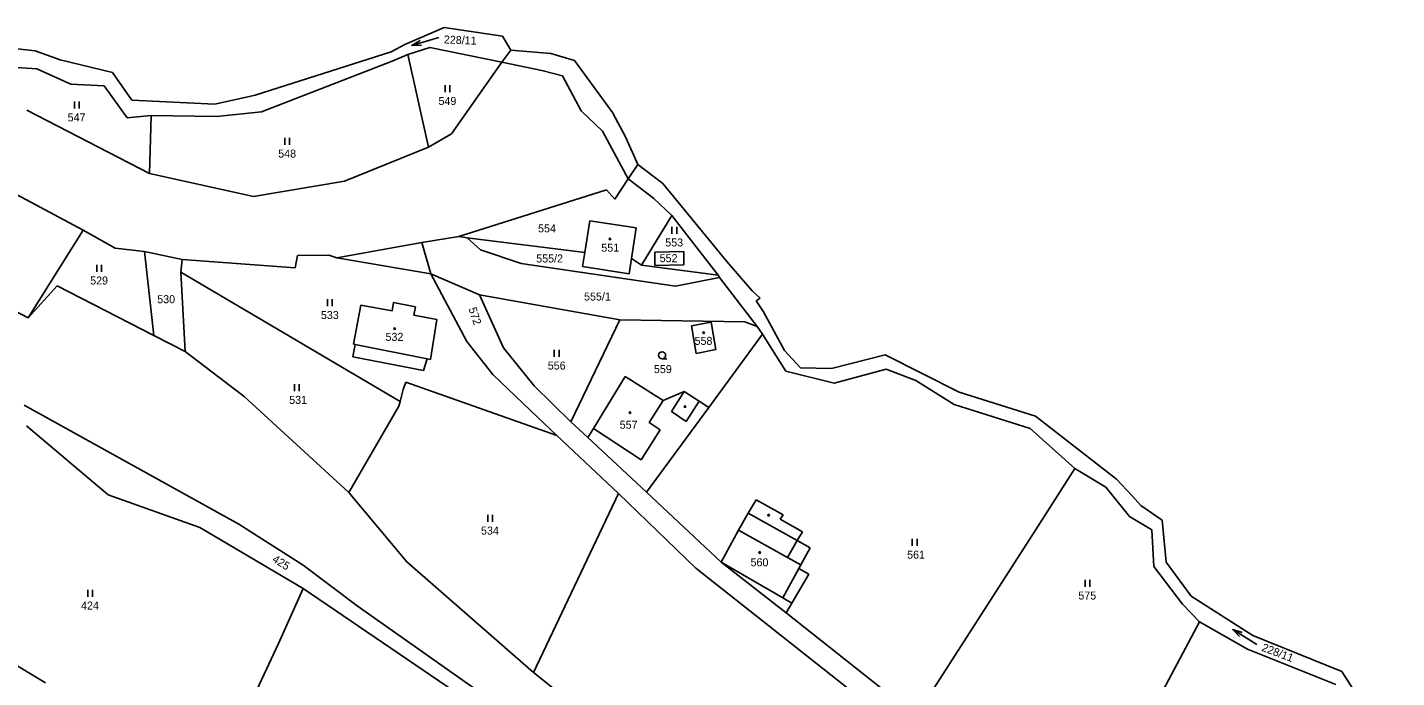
# Model space of a CAD drawing. Extents: x -670359 to -668019, y -978807 to -976674.
# Drawn here: x -668397.5 to -668106.7, y -976872.6 to -976734.6 of the extents above; entities that cross this region are included whole.
import ezdxf

# ---------------------------------------------------------------- set-up
doc = ezdxf.new("R2010")
doc.units = 0
for name, color, linetype in [('Hranice kat_území', 7, 'Continuous'), ('Hranice parcel', 7, 'Continuous'), ('Parcelní čísla', 7, 'Continuous'), ('Vnitřní kresba', 7, 'Continuous'), ('Značky budov', 7, 'Continuous'), ('Značky kultur', 7, 'Continuous')]:
    doc.layers.add(name, color=color, linetype=linetype)

msp = doc.modelspace()

# ---------------------------------------------------------------- linework, layer by layer
at = {"layer": 'Hranice kat_území'}
for points in [[(-668317.37, -976738.24), (-668309.02, -976734.61)], [(-668309.02, -976734.61), (-668296.58, -976736.5)], [(-668296.58, -976736.5), (-668294.82, -976739.45)], [(-668401.56, -976738.95), (-668395.86, -976739.55)], [(-668395.86, -976739.55), (-668390.58, -976741.48)], [(-668349.12, -976748.96), (-668320.23, -976739.79)], [(-668320.23, -976739.79), (-668317.37, -976738.24)], [(-668294.82, -976739.45), (-668286.37, -976740.15)], [(-668390.58, -976741.48), (-668379.43, -976744.15)], [(-668286.37, -976740.15), (-668281.3, -976741.62)], [(-668281.3, -976741.62), (-668273.27, -976752.67)], [(-668379.43, -976744.15), (-668375.33, -976750.07)], [(-668375.33, -976750.07), (-668357.69, -976750.92)], [(-668357.69, -976750.92), (-668349.12, -976748.96)], [(-668273.27, -976752.67), (-668270.5, -976757.82)], [(-668270.5, -976757.82), (-668267.83, -976763.68)], [(-668267.83, -976763.68), (-668262.57, -976767.7)], [(-668262.57, -976767.7), (-668248.96, -976784.27)], [(-668248.96, -976784.27), (-668243.58, -976790.53)], [(-668243.58, -976790.53), (-668241.91, -976792.09)], [(-668241.91, -976792.09), (-668242.75, -976792.62)], [(-668242.75, -976792.62), (-668241.2, -976794.95)], [(-668241.2, -976794.95), (-668236.71, -976803.16)], [(-668236.71, -976803.16), (-668233.34, -976806.82)], [(-668233.34, -976806.82), (-668226.72, -976807)], [(-668226.72, -976807), (-668215.36, -976804.09)], [(-668215.36, -976804.09), (-668199.61, -976811.98)], [(-668199.61, -976811.98), (-668183.37, -976817.09)], [(-668183.37, -976817.09), (-668166.16, -976830.45)], [(-668166.16, -976830.45), (-668162.87, -976834.03)], [(-668161.05, -976836.02), (-668162.87, -976834.03)], [(-668161.05, -976836.02), (-668156.53, -976839.16)], [(-668156.53, -976839.16), (-668155.66, -976848.08)], [(-668155.66, -976848.08), (-668150.37, -976855.32)], [(-668150.37, -976855.32), (-668137.24, -976863.65)], [(-668137.24, -976863.65), (-668118.31, -976871.28)], [(-668118.31, -976871.28), (-668106.7, -976889.43)]]:
    msp.add_lwpolyline(points, dxfattribs=at)
at = {"layer": 'Hranice parcel'}
for points in [[(-668316.7, -976740.34), (-668312.03, -976738.87)], [(-668312.03, -976738.87), (-668296.72, -976741.98)], [(-668347.77, -976752.51), (-668320.02, -976741.74)], [(-668320.02, -976741.74), (-668316.7, -976740.34)], [(-668316.7, -976740.34), (-668312.35, -976759.99)], [(-668307.41, -976757.21), (-668296.72, -976741.98)], [(-668296.72, -976741.98), (-668288.24, -976743.73)], [(-668402.02, -976742.95), (-668395.53, -976743.38)], [(-668395.53, -976743.38), (-668388.26, -976746.62)], [(-668288.24, -976743.73), (-668283.85, -976744.87)], [(-668283.85, -976744.87), (-668279.91, -976752.34)], [(-668388.26, -976746.62), (-668381.21, -976747)], [(-668381.21, -976747), (-668376.3, -976753.79)], [(-668397.66, -976752.14), (-668371.58, -976765.6)], [(-668376.3, -976753.79), (-668371.2, -976753.33)], [(-668371.2, -976753.33), (-668371.58, -976765.6)], [(-668371.2, -976753.33), (-668357.33, -976753.54)], [(-668357.33, -976753.54), (-668347.77, -976752.51)], [(-668279.91, -976752.34), (-668275.35, -976756.6)], [(-668385.67, -976777.65), (-668426.4, -976755.93)], [(-668312.35, -976759.99), (-668307.41, -976757.21)], [(-668275.35, -976756.6), (-668269.92, -976766.72)], [(-668330.18, -976767.21), (-668312.35, -976759.99)], [(-668371.58, -976765.6), (-668349.47, -976770.48)], [(-668349.47, -976770.48), (-668330.18, -976767.21)], [(-668274.5, -976769.06), (-668305.89, -976779.01)], [(-668272.76, -976771.04), (-668274.5, -976769.06)], [(-668269.92, -976766.72), (-668272.76, -976771.04)], [(-668269.92, -976766.72), (-668264.48, -976770.88)], [(-668264.48, -976770.88), (-668260.63, -976774.5)], [(-668260.63, -976774.5), (-668267.07, -976785.08)], [(-668260.63, -976774.5), (-668250.82, -976787.21)], [(-668397.37, -976796.2), (-668385.67, -976777.65)], [(-668378.9, -976781.43), (-668385.67, -976777.65)], [(-668278.06, -976775.64), (-668279.13, -976782.36)], [(-668268.24, -976777.16), (-668278.06, -976775.64)], [(-668269.2, -976783.61), (-668268.24, -976777.16)], [(-668313.72, -976780.25), (-668331.82, -976783.48)], [(-668305.89, -976779.01), (-668313.72, -976780.25)], [(-668305.89, -976779.01), (-668304.08, -976779.24)], [(-668279.13, -976782.36), (-668304.08, -976779.24)], [(-668304.08, -976779.24), (-668301.3, -976781.81)], [(-668372.63, -976782.13), (-668378.9, -976781.43)], [(-668364.63, -976783.85), (-668372.63, -976782.13)], [(-668370.63, -976800), (-668372.63, -976782.13)], [(-668340.12, -976783), (-668340.61, -976785.62)], [(-668333.49, -976782.93), (-668340.12, -976783)], [(-668331.82, -976783.48), (-668333.49, -976782.93)], [(-668331.82, -976783.48), (-668311.81, -976786.89)], [(-668301.3, -976781.81), (-668292.66, -976784.73)], [(-668279.6, -976785.37), (-668279.13, -976782.36)], [(-668264.25, -976785.1), (-668264.23, -976782.28)], [(-668264.23, -976782.28), (-668258.12, -976782.19)], [(-668258.12, -976782.19), (-668258.06, -976785)], [(-668364.91, -976786.53), (-668364.63, -976783.85)], [(-668340.61, -976785.62), (-668364.63, -976783.85)], [(-668292.66, -976784.73), (-668259.88, -976789.53)], [(-668269.69, -976786.89), (-668279.6, -976785.37)], [(-668269.2, -976783.61), (-668269.69, -976786.89)], [(-668267.07, -976785.08), (-668269.2, -976783.61)], [(-668250.82, -976787.21), (-668267.07, -976785.08)], [(-668258.06, -976785), (-668264.25, -976785.1)], [(-668318.37, -976813.96), (-668364.91, -976786.53)], [(-668364.03, -976803.41), (-668364.91, -976786.53)], [(-668311.81, -976786.89), (-668304.15, -976801.28)], [(-668301.5, -976791.38), (-668311.81, -976786.89)], [(-668259.88, -976789.53), (-668250.48, -976787.65)], [(-668250.82, -976787.21), (-668250.48, -976787.65)], [(-668242.49, -976798.06), (-668250.48, -976787.65)], [(-668391.17, -976789.43), (-668397.37, -976796.2)], [(-668370.63, -976800), (-668391.17, -976789.43)], [(-668271.71, -976796.64), (-668301.5, -976791.38)], [(-668296.36, -976802.58), (-668301.5, -976791.38)], [(-668397.37, -976796.2), (-668403.65, -976792.99)], [(-668328.24, -976801.84), (-668326.72, -976793.55)], [(-668326.72, -976793.55), (-668320.06, -976794.77)], [(-668320.06, -976794.77), (-668319.77, -976792.97)], [(-668319.77, -976792.97), (-668315.08, -976793.92)], [(-668315.08, -976793.92), (-668315.46, -976795.65)], [(-668315.46, -976795.65), (-668310.53, -976796.57)], [(-668310.53, -976796.57), (-668311.87, -976805.08)], [(-668271.71, -976796.64), (-668282.12, -976818.27)], [(-668271.71, -976796.64), (-668245.13, -976797.1)], [(-668256.43, -976797.94), (-668252.25, -976797.17)], [(-668255.49, -976803.8), (-668256.43, -976797.94)], [(-668252.25, -976797.17), (-668251.31, -976802.95)], [(-668242.49, -976798.06), (-668245.13, -976797.1)], [(-668242.49, -976798.06), (-668241.35, -976799.71)], [(-668364.03, -976803.41), (-668370.63, -976800)], [(-668241.35, -976799.71), (-668252.78, -976815.25)], [(-668241.35, -976799.71), (-668236.4, -976807.55)], [(-668351.45, -976812.91), (-668364.03, -976803.41)], [(-668328.36, -976804.51), (-668327.92, -976801.89)], [(-668327.92, -976801.89), (-668328.24, -976801.84)], [(-668304.15, -976801.28), (-668298.65, -976808.25)], [(-668289.86, -976810.69), (-668296.36, -976802.58)], [(-668251.31, -976802.95), (-668255.49, -976803.8)], [(-668313.4, -976807.42), (-668328.36, -976804.51)], [(-668312.62, -976804.92), (-668313.4, -976807.42)], [(-668311.87, -976805.08), (-668312.62, -976804.92)], [(-668298.65, -976808.25), (-668290.66, -976815.93)], [(-668270.58, -976808.71), (-668277.29, -976819.73)], [(-668262.47, -976813.8), (-668270.58, -976808.71)], [(-668236.4, -976807.55), (-668226.15, -976810.07)], [(-668226.15, -976810.07), (-668215.11, -976807.12)], [(-668215.11, -976807.12), (-668208.82, -976809.51)], [(-668208.82, -976809.51), (-668200.7, -976814.59)], [(-668317.72, -976811.42), (-668318.37, -976813.96)], [(-668317.12, -976809.92), (-668317.72, -976811.42)], [(-668285.03, -976821.2), (-668317.12, -976809.92)], [(-668282.12, -976818.27), (-668289.86, -976810.69)], [(-668258, -976811.87), (-668262.47, -976813.8)], [(-668254.8, -976813.94), (-668258, -976811.87)], [(-668352.59, -976840.01), (-668398.2, -976814.79)], [(-668329.23, -976833.33), (-668351.45, -976812.91)], [(-668329.23, -976833.33), (-668318.63, -976814.97)], [(-668318.63, -976814.97), (-668318.37, -976813.96)], [(-668252.78, -976815.25), (-668266.03, -976833.25)], [(-668252.78, -976815.25), (-668254.8, -976813.94)], [(-668200.7, -976814.59), (-668184.54, -976819.71)], [(-668290.66, -976815.93), (-668285.03, -976821.2)], [(-668278.47, -976821.66), (-668282.12, -976818.27)], [(-668397.73, -976819.17), (-668380.39, -976833.81)], [(-668285.03, -976821.2), (-668271.96, -976833.48)], [(-668277.29, -976819.73), (-668278.47, -976821.66)], [(-668184.54, -976819.71), (-668175.02, -976828.18)], [(-668266.03, -976833.25), (-668278.47, -976821.66)], [(-668175.02, -976828.18), (-668182.88, -976840.49)], [(-668175.02, -976828.18), (-668168.47, -976832.15)], [(-668168.47, -976832.15), (-668163.46, -976838.37)], [(-668380.39, -976833.81), (-668360.88, -976840.74)], [(-668316.89, -976848), (-668329.23, -976833.33)], [(-668271.96, -976833.48), (-668290.02, -976871.49)], [(-668271.96, -976833.48), (-668255.57, -976849.35)], [(-668250.19, -976848.05), (-668266.03, -976833.25)], [(-668242.74, -976834.86), (-668244.45, -976837.7)], [(-668237.01, -976838.03), (-668242.74, -976834.86)], [(-668244.45, -976837.7), (-668246.45, -976841.31)], [(-668237.63, -976838.98), (-668237.01, -976838.03)], [(-668163.46, -976838.37), (-668158.72, -976841.24)], [(-668360.88, -976840.74), (-668338.97, -976853.68)], [(-668338.94, -976848.69), (-668352.59, -976840.01)], [(-668246.45, -976841.31), (-668250.19, -976848.05)], [(-668232.92, -976841.62), (-668237.63, -976838.98)], [(-668234.01, -976843.5), (-668232.92, -976841.62)], [(-668182.88, -976840.49), (-668208.77, -976880.71)], [(-668158.72, -976841.24), (-668158.29, -976849)], [(-668231.24, -976845.04), (-668234.01, -976843.5)], [(-668233.22, -976848.65), (-668231.24, -976845.04)], [(-668327.45, -976857.34), (-668338.94, -976848.69)], [(-668290.02, -976871.49), (-668316.89, -976848)], [(-668255.57, -976849.35), (-668211.38, -976884.21)], [(-668236.32, -976858.8), (-668250.19, -976848.05)], [(-668233.7, -976849.42), (-668233.22, -976848.65)], [(-668231.55, -976850.64), (-668233.7, -976849.42)], [(-668158.29, -976849), (-668152.21, -976856.96)], [(-668235.13, -976856.77), (-668231.55, -976850.64)], [(-668338.97, -976853.68), (-668344.16, -976865.34)], [(-668296.59, -976882.46), (-668338.97, -976853.68)], [(-668295.33, -976879.99), (-668327.45, -976857.34)], [(-668236.32, -976858.8), (-668235.13, -976856.77)], [(-668208.77, -976880.71), (-668236.32, -976858.8)], [(-668152.21, -976856.96), (-668148.6, -976860.72)], [(-668148.6, -976860.72), (-668156.29, -976875.26)], [(-668148.6, -976860.72), (-668138.39, -976866.51)], [(-668344.16, -976865.34), (-668351.37, -976880.76)], [(-668138.39, -976866.51), (-668119.61, -976874.06)], [(-668402.03, -976868.63), (-668393.67, -976873.69)], [(-668258.01, -976896.92), (-668290.02, -976871.49)]]:
    msp.add_lwpolyline(points, dxfattribs=at)
at = {"layer": 'Vnitřní kresba'}
for points in [[(-668296.72, -976741.98), (-668294.82, -976739.45)], [(-668267.83, -976763.68), (-668269.92, -976766.72)], [(-668313.72, -976780.25), (-668311.81, -976786.89)], [(-668327.92, -976801.89), (-668312.62, -976804.92)], [(-668258, -976811.87), (-668260.69, -976816.1)], [(-668262.47, -976813.8), (-668265.43, -976818.46)], [(-668257.56, -976818.26), (-668254.8, -976813.94)], [(-668265.43, -976818.46), (-668263.1, -976819.98)], [(-668260.69, -976816.1), (-668257.56, -976818.26)], [(-668267.16, -976826.37), (-668277.29, -976819.73)], [(-668263.1, -976819.98), (-668267.16, -976826.37)], [(-668244.45, -976837.7), (-668234.01, -976843.5)], [(-668246.45, -976841.31), (-668236.07, -976847.07)], [(-668234.01, -976843.5), (-668236.07, -976847.07)], [(-668236.07, -976847.07), (-668233.22, -976848.65)], [(-668250.19, -976848.05), (-668237.06, -976855.66)], [(-668233.7, -976849.42), (-668237.06, -976855.66)], [(-668237.06, -976855.66), (-668235.13, -976856.77)]]:
    msp.add_lwpolyline(points, dxfattribs=at)
at = {"layer": 'Značky budov'}
for centre in [(-668273.77, -976779.49), (-668319.52, -976798.52), (-668253.88, -976799.37), (-668269.54, -976816.34), (-668241.99, -976846.04)]:
    msp.add_circle(centre, 0.175, dxfattribs=at)
at = {"layer": 'Značky kultur'}
for p, q in [((-668310.13, -976736.76), (-668315.89, -976738.44)), ((-668308.81, -976746.87), (-668308.81, -976748.37)), ((-668307.81, -976748.37), (-668307.81, -976746.87)), ((-668387.53, -976750.35), (-668387.53, -976751.85)), ((-668386.53, -976751.85), (-668386.53, -976750.35)), ((-668342.81, -976758.03), (-668342.81, -976759.53)), ((-668341.81, -976759.53), (-668341.81, -976758.03)), ((-668260.61, -976776.89), (-668260.61, -976778.39)), ((-668259.61, -976778.39), (-668259.61, -976776.89)), ((-668382.79, -976784.96), (-668382.79, -976786.46)), ((-668381.79, -976786.46), (-668381.79, -976784.96)), ((-668333.75, -976792.29), (-668333.75, -976793.79)), ((-668332.75, -976793.79), (-668332.75, -976792.29)), ((-668285.6, -976803.01), (-668285.6, -976804.51)), ((-668284.6, -976804.51), (-668284.6, -976803.01)), ((-668262.71, -976804.93), (-668261.71, -976804.93)), ((-668340.8, -976810.29), (-668340.8, -976811.79)), ((-668339.8, -976811.79), (-668339.8, -976810.29)), ((-668299.71, -976838.03), (-668299.71, -976839.53)), ((-668298.71, -976839.53), (-668298.71, -976838.03)), ((-668209.56, -976843.14), (-668209.56, -976844.64)), ((-668208.56, -976844.64), (-668208.56, -976843.14)), ((-668172.87, -976851.81), (-668172.87, -976853.31)), ((-668171.87, -976853.31), (-668171.87, -976851.81)), ((-668384.66, -976853.93), (-668384.66, -976855.43)), ((-668383.66, -976855.43), (-668383.66, -976853.93)), ((-668136.37, -976865.53), (-668141.49, -976862.39))]:
    msp.add_line(p, q, dxfattribs=at)
for points in [[(-668313.83, -976738.36), (-668315.89, -976738.44), (-668314.11, -976737.4)], [(-668140.04, -976863.86), (-668141.49, -976862.39), (-668139.52, -976863.01)]]:
    msp.add_lwpolyline(points, dxfattribs=at)
for centre, radius in [((-668273.77, -976779.49), 0.175), ((-668319.52, -976798.52), 0.175), ((-668253.88, -976799.37), 0.175), ((-668262.71, -976804.18), 0.75), ((-668257.85, -976815.08), 0.175), ((-668269.54, -976816.34), 0.175), ((-668240.07, -976838.12), 0.175), ((-668241.99, -976846.04), 0.175)]:
    msp.add_circle(centre, radius, dxfattribs=at)

# ---------------------------------------------------------------- texts
at = {"layer": 'Parcelní čísla'}
for s, rotation, p in [('228/11', 357.6975, (-668309.09, -976738)), ('572', 288.1527, (-668303.83, -976794.3)), ('425', 327.8627, (-668345.66, -976847.86)), ('228/11', 339.191, (-668135.5, -976866.83))]:
    msp.add_text(s, height=1.7, rotation=rotation, dxfattribs=at).set_placement(p)
for s, p in [('549', (-668310.2, -976751.07)), ('547', (-668388.96, -976754.55)), ('548', (-668344.24, -976762.23)), ('554', (-668289.05, -976778.1)), ('551', (-668275.62, -976782.2)), ('553', (-668262.04, -976781.09)), ('555/2', (-668289.44, -976784.49)), ('552', (-668263.22, -976784.43)), ('529', (-668384.18, -976789.16)), ('530', (-668369.94, -976793.13)), ('555/1', (-668279.28, -976792.56)), ('533', (-668335.18, -976796.49)), ('532', (-668321.45, -976801.12)), ('558', (-668255.81, -976801.97)), ('556', (-668286.99, -976807.21)), ('559', (-668264.44, -976807.96)), ('531', (-668341.91, -976814.49)), ('557', (-668271.71, -976819.76)), ('534', (-668301.17, -976842.23)), ('560', (-668243.92, -976848.96)), ('561', (-668210.67, -976847.34)), ('575', (-668174.3, -976856.01)), ('424', (-668386.12, -976858.13))]:
    msp.add_text(s, height=1.7, dxfattribs=at).set_placement(p)

doc.saveas('drawing.dxf')
